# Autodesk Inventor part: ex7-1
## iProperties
Author: Administrator
Revision Number: A
Created: 2001-10
Part Number: ex7-1
Description: WHEEL
Document SubType Name: Modeling
Designer: E. MOSS
Control State: 0
Master: False
Checked Out: False
PropertySet Name: Design Tracking Control
Shininess: 20.0
Angle Display Precision: 2
Document Length Units: 11272
Document Angle Units: 11286
Document Time Units: 11279
Document Mass Units: 11290
Document Length Units Precision: 3
Document Angle Units Precision: 2
Compacted: False
PropertySet Name: _Private Model Information
Density: 0.0
Volumn: 0.0
Area: 0.0
PropertySet Name: Model Information
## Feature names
1. Revolution1
2. Tire [Revolution]
3. Extrusion1
4. Circular Pattern1
